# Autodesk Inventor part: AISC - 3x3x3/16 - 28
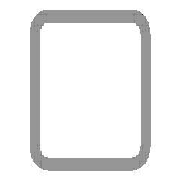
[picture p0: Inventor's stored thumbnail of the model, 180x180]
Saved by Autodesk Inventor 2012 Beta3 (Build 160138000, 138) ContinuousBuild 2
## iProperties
IsCustomPart: 1
Created: 2011-01
Part Number: AISC - 3x3x3/16 - 28
Material: Steel, Mild
Description: Tube
Document SubType Name: Modeling
Standard: ANSI
Designer: Beta-8540w
Standards Organization: ANSI
Language: en-US
Size Designation: 3x3x3/16
Categories: <MemberInstance><Categories><Category DisplayName="Structural Shapes" InternalName="089c4875-fa83-4c05-b084-43b9cc11f5ed" Mnemonic="GRDR"><CategoryParameter Dis
Stock Number: 3x3x3/16
Density: 7.86 g/cm^3
G_L: 28.000 in
G_W: 3.000 in
G_H: 3.000 in
_CCFamilyMember: 9
_CCFamilyDisplayName: ANSI AISC (Square) - Tube
_FrameMemberDoc: Frame Member File
_Version: 15.0.0
_GetPNFromCC: 1
Author: Beta-8540w
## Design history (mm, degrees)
node "Start plane"
node "End plane"
sketch "Sketch"
  geometry: L1 (-38.1, -28.575)-(-38.1, 28.575); L2 (-28.575, 38.1)-(28.575, 38.1); L3 (38.1, 28.575)-(38.1, -28.575); L4 (28.575, -38.1)-(-28.575, -38.1); L5 (-28.575, 33.337)-(28.575, 33.338); L6 (33.338, 28.575)-(33.338, -28.575); L7 (28.575, -33.337)-(-28.575, -33.338); L8 (-33.338, -28.575)-(-33.338, 28.575); L9 (0, 56.102)-(0, -56.102) reference; L10 (-56.102, 0)-(56.102, 0) reference; A1 r 9.525 centre (-28.575, -28.575) between (-38.1, -28.575) and (-28.575, -38.1); A2 r 9.525 centre (-28.575, 28.575) between (-28.575, 38.1) and (-38.1, 28.575); A3 r 9.525 centre (28.575, 28.575) between (38.1, 28.575) and (28.575, 38.1); A4 r 9.525 centre (28.575, -28.575) between (28.575, -38.1) and (38.1, -28.575); A5 r 4.763 centre (-28.575, 28.575) between (-28.575, 33.337) and (-33.338, 28.575); A6 r 4.763 centre (28.575, 28.575) between (33.338, 28.575) and (28.575, 33.338); A7 r 4.763 centre (28.575, -28.575) between (28.575, -33.337) and (33.338, -28.575); A8 r 4.763 centre (-28.575, -28.575) between (-33.338, -28.575) and (-28.575, -33.338)
  constraints: 16 end point, 16 point on circle, 8 centre point, 8 tangent, 4 parallel, 3 equal radius, 2 perpendicular, 7 other
  dimensions: "d10" = 76.2 distance between parallel lines of L2 L4 (= G_H); "d11" = 76.2 distance between parallel lines of L1 L3 (= G_W); "d12" = 4.7625 distance between parallel lines of L3 L6 (= G_T); "d15" = 38.1 distance between parallel lines of L2 L10 (= 0.5 x d10); "d16" = 38.1 distance between parallel lines of L9 L3 (= 0.5 x d11); "d17" = 9.525 radius of A1 (= G_IR)
extrude "Body" new body sketch "Sketch" stored distance "d3" = 711.2 (= G_L); taper "d4" = 0 deg
node "Driven Length"
  sketch "Sketch3"
    geometry: L1 (0, 0)-(10, 0) reference
    constraints: 2 end point, 1 horizontal
  workplane "Work Plane3"
  sketch "Sketch4"
    geometry: L1 (-2, 0)-(12, 0) reference; L2 (-2, 711.2)-(12, 711.2) reference
    dimensions: "d19" = 711.2 distance between parallel lines of L1 L2 (derived)
body "Solid1"
other parameters: "G_W" = 76.2 [user parameter; used in 1 equation term], "G_H" = 76.2 [user parameter; used in 1 equation term], "G_T" = 4.7625 [user parameter; used in 1 equation term], "G_IR" = 9.525 [user parameter; used in 1 equation term], "G_L" = 711.2 (= d19) [user parameter; used in 1 equation term], "G_OFFSET_START" = 0 [user parameter; used in 1 equation term], "G_OFFSET_END" = 0 [user parameter; used in 1 equation term], "d13" = 0 (computed from G_OFFSET_START), "d14" = 711.2 (= G_OFFSET_END + B_L), "B_L" = 711.2 [user parameter; used in 1 equation term], "d18" = 90 deg
